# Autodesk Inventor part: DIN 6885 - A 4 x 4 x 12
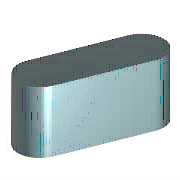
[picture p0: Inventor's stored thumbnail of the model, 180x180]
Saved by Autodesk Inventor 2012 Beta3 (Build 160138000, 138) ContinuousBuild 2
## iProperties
IsCustomPart: 0
Created: 2010-11
Part Number: DIN 6885 - A 4 x 4 x 12
Material: Steel, Mild
Description: Parallel Key
Document SubType Name: Modeling
Standard: DIN 6885
Designer: Beta-8540w
Standards Organization: DIN
Language: en-US
Size Designation: A 4 x 4 x 12
Categories: <MemberInstance><Categories><Category DisplayName="Shaft Parts" InternalName="7f7aeb1f-a693-4053-b835-cee3144e0d98" Mnemonic="SHFT"><Category DisplayName="Keys"
Density: 1 g/cm^3
Author: Beta-8540w
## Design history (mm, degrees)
sketch "Sketch1"
  geometry: L1 (2, 2)-(10, 2); L2 (10, -2)-(2, -2); L3 (0, 9.4)-(0, -7.4) reference; L4 (-5, 0)-(30, 0) reference; L5 (12, 0)-(12, 7); A1 r 2 centre (2, 0) between (2, 2) and (2, -2); A2 r 2 centre (10, 0) between (10, -2) and (10, 2)
  constraints: 6 end point, 5 point on circle, 4 tangent, 3 point on line, 2 centre point, 1 horizontal, 1 parallel, 1 perpendicular
  dimensions: "d0" = 2 radius of A1 (= 0.5 x PB); "d8" = 2 radius of A2 (= 0.5 x PB); "d9" = 12 distance between parallel lines of L5 L3 (= NLG)
extrude "Body1" new body sketch "Sketch1" taper "d3" = 0 deg; stored distance "d4" = 10
workplane "Work Plane3"
body "Solid1"
workplane "Work Plane1"
workplane "Work Plane2"
other parameters: "d1" = -2.5 (= -PNT), "d2" = 1.5 (= PH - PNT), "NLG" = 12 [user parameter; used in 3 equation terms], "PB" = 4 [user parameter; used in 2 equation terms], "PNT" = 2.5 [user parameter; used in 2 equation terms], "PH" = 4 [user parameter; used in 1 equation term], "d7" = 0, "d15" = 0, "d16" = 0, "d17" = 0, "RR" = 0.001 [user parameter], "PHH" = 0 [user parameter], "WDMAX" = 12 [user parameter], "PLB1" = 12 (= NLG) [user parameter], "PLB2" = 12 (= NLG) [user parameter], "PUEB" = 1.8 [user parameter]
